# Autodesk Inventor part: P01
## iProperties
Created: 2007-12
Part Number: P01
Document SubType Name: Modeling
Designer: UJA2299
Density: 1 g/cm^3
Author: UJA2299
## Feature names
1. 押し出し1 [Extrusion]
2. 押し出し2 [Extrusion]
3. 押し出し3 [Extrusion]
